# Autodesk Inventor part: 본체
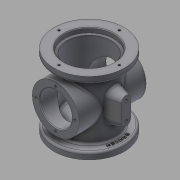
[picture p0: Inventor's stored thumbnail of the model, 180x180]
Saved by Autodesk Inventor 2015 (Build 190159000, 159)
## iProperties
Created: 2018-02
Part Number: 본체
Material: 일반
Document SubType Name: Modeling
Designer: SCD-A03
Density: 1 g/cm^3
Appearance: 기본값
Author: SCD-A03
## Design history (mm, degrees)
sketch "스케치1"
  geometry: L1 (-38, 44)-(0, 44); L2 (0, 44)-(0, -44); L3 (0, -44)-(-38, -44); L4 (-38, -44)-(-38, 44); L5 (0, 44)-(-52.5, 44); L6 (-52.5, 44)-(-52.5, 54); L7 (-52.5, 54)-(0, 54); L8 (0, 54)-(0, 44); L9 (0, -44)-(-52.5, -44); L10 (-52.5, -44)-(-52.5, -54); L11 (-52.5, -54)-(0, -54); L12 (0, -54)-(0, -44); 1 further point
  constraints: 24 end point, 6 parallel, 3 horizontal, 3 perpendicular, 1 midpoint
  dimensions: "d0" = 76 diameter of L4 L2; "d1" = 105 diameter of L6 L8; "d2" = 105 diameter of L10 L2; "d3" = 10 distance of L5.end L6.end; "d4" = 10 distance of L9.end L10.end; "d5" = 108 distance between parallel lines of L11 L7; "d6" = 54 distance from line of point (0, 0) L11
revolve "회전1" sketch "스케치1" stored, may be unused: angle "d7" = 90 deg
node "작업 평면1"
sketch "스케치2"
  geometry: C1 r 35 at (0, 0); 1 further point
  constraints: 1 centre point, 1 coincident
  dimensions: "d9" = 70 diameter of C1
extrude "돌출1" join sketch "스케치2" distance "d10" = 100; taper "d11" = 0 deg
sketch "스케치3"
  geometry: C1 r 37 at (0, 0); 1 further point
  constraints: 1 centre point, 1 coincident
  dimensions: "d12" = 74 diameter of C1
extrude "돌출2" cut sketch "스케치3" distance "d13" = 7; taper "d14" = 0 deg
sketch "스케치4"
  geometry: C1 r 33 at (0, 0); 1 further point
  constraints: 1 centre point, 1 coincident
  dimensions: "d15" = 66 diameter of C1
extrude "돌출3" cut sketch "스케치4" distance "d16" = 79; taper "d17" = 0 deg
sketch "스케치5"
  geometry: C1 r 34 at (0, 0); 1 further point
  constraints: 1 centre point, 1 coincident
  dimensions: "d18" = 68 diameter of C1
extrude "돌출4" cut sketch "스케치5" distance "d19" = 16; taper "d20" = 0 deg
hole "구멍1" diameter "d23" = 48; stored, may be unused: countersink angle "d27" = 90 deg, drill point angle "d29" = 118 deg; dims "d21" = 10, "d22" = 10, "d24" = 6, "d25" = 4, "d26" = 2, "d28" = 8
sketch "스케치6"
  geometry: C1 r 5 at (0, 0); 1 further point
  constraints: 1 centre point, 1 coincident
  dimensions: "d30" = 10 diameter of C1
extrude "돌출5" cut sketch "스케치6" stored distance "d31" = 16; taper "d32" = 0 deg
node "작업 평면2"
sketch "스케치7"
  geometry: L1 (0, 20)-(0, -20); L2 (-7, 13)-(-7, -13); L3 (7, -13)-(7, 13); A1 r 7 centre (0, 13) between (7, 13) and (-7, 13); A2 r 7 centre (0, -13) between (-7, -13) and (7, -13); 2 further points
  constraints: 8 end point, 6 point on circle, 4 tangent, 2 centre point, 2 point on line, 1 coincident, 1 midpoint, 1 parallel, 1 vertical
  dimensions: "d34" = 40 distance of L1.start L1.end; "d35" = 7 radius of A1
extrude "돌출6" join sketch "스케치7" stored distance "d36" = 16; taper "d37" = 0 deg
feature "면 기울기1" dims angle "d38" = 15 deg
sketch "스케치11" dims "d39" = 58
  geometry: L1 (0, 0)-(0, 29); 2 further points
  constraints: 2 coincident, 2 end point, 1 vertical, 1 vertical alignment, 2 other
hole "구멍2" sketch "스케치11" at (0, 29) diameter "d40" = 3.242; stored, may be unused: countersink angle "d44" = 90 deg, drill point angle "d46" = 118 deg; dims "d41" = 4, "d42" = 4, "d43" = 2, "d45" = 6
sketch "스케치12" dims "d50" = 90
  geometry: L1 (0, 0)-(0, 45); 2 further points
  constraints: 2 coincident, 2 end point, 1 vertical, 1 vertical alignment, 2 other
hole "구멍3" sketch "스케치12" at (0, 45) diameter "d51" = 3.242; stored, may be unused: countersink angle "d55" = 90 deg, drill point angle "d57" = 118 deg; dims "d52" = 4, "d53" = 4, "d54" = 2, "d56" = 6
chamfer "모따기1" distance "d61" = 1; stored, may be unused: second distance "d62" = 2, angle "d63" = 45 deg
fillet "모깎기1" dims "d64" = 3
sketch "스케치13"
  geometry: L1 (-7, 13)-(-7, -13) reference; L2 (7, -13)-(7, 13) reference; A1 r 7 centre (0, -13) between (-7, -13) and (7, -13) reference; A2 r 7 centre (0, 13) between (7, 13) and (-7, 13) reference; 3 further points
  constraints: 2 coincident
hole "구멍4" sketch "스케치13" at (0, 13), (0, -13) diameter "d65" = 4.134; stored, may be unused: countersink angle "d69" = 90 deg, drill point angle "d71" = 118 deg; dims "d66" = 6, "d67" = 4, "d68" = 2, "d70" = 8
sketch "스케치14"
  geometry: C1 r 43 at (0, 0); 1 further point
  constraints: 1 centre point, 1 coincident, 1 other
  dimensions: "d72" = 86 diameter of C1
feature "엠보싱1" sketch "스케치14" dims "d0" = 76, "d1" = 105, "d2" = 105, "d3" = 10, "d4" = 10, "d5" = 108, "d6" = 54, "d12" = 74, "d73" = 0.5, "d74" = 0
fillet "모깎기2" dims "d75" = 3
node "솔리드1"
pattern_circular "원형 패턴1" dims angle "d48" = 360 deg
mirror "대칭1"
pattern_circular "원형 패턴2" dims angle "d59" = 360 deg
node "투영된 루프1"
other parameters: "d33" = 55
